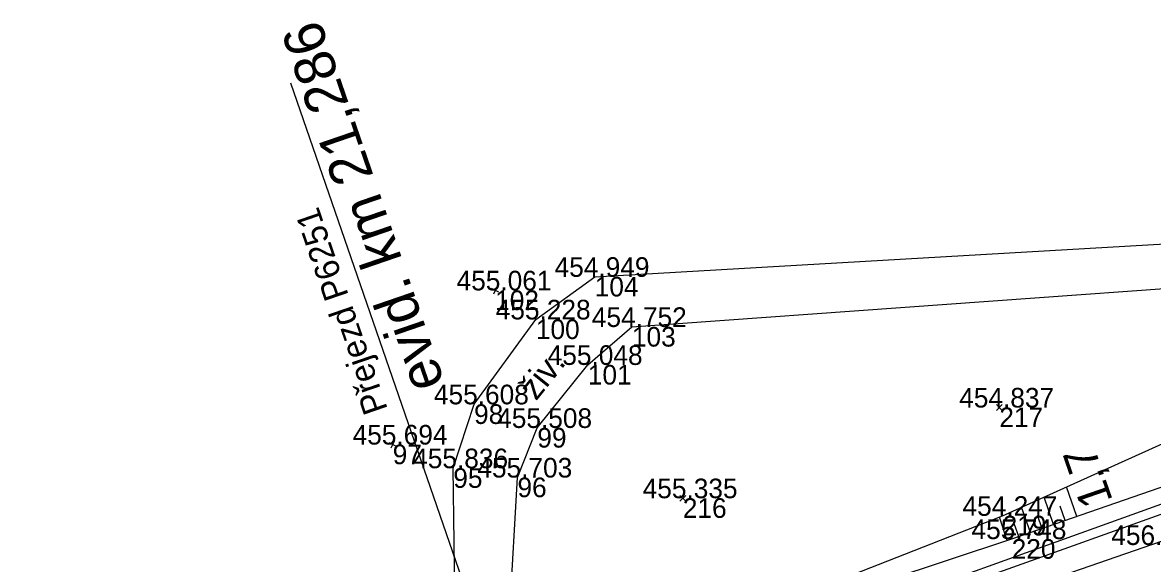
# Model space of a CAD drawing. Extents: x -751615 to -750797, y -1114905 to -1114561.
# Drawn here: x -750936.3 to -750867.3, y -1114593.7 to -1114560.6 of the extents above; entities that cross this region are included whole.
import ezdxf

# ---------------------------------------------------------------- set-up
doc = ezdxf.new("R2010")
doc.units = 0
for name, color, linetype in [('Vrstva 1', 7, 'Continuous'), ('Vrstva 4', 7, 'Continuous'), ('Vrstva 48', 7, 'Continuous'), ('Vrstva 49', 7, 'Continuous'), ('Vrstva 51', 7, 'Continuous'), ('Vrstva 60', 7, 'Continuous'), ('Vrstva 61', 7, 'Continuous')]:
    doc.layers.add(name, color=color, linetype=linetype)

msp = doc.modelspace()

# ---------------------------------------------------------------- linework, layer by layer
at = {"layer": 'Vrstva 1'}
msp.add_lwpolyline([(-750820.337, -1114576.326), (-750829.58, -1114579.518), (-750838.838, -1114582.712), (-750848.38, -1114586.005), (-750858.075, -1114589.346), (-750867.336, -1114592.541), (-750876.526, -1114595.715), (-750885.989, -1114598.98), (-750895.385, -1114602.229), (-750902.991, -1114604.843), (-750908.211, -1114606.647), (-750914.742, -1114608.898), (-750924.077, -1114612.114), (-750933.495, -1114615.368), (-750942.896, -1114618.61), (-750952.239, -1114621.829), (-750961.799, -1114625.127), (-750971.586, -1114628.505), (-750981.562, -1114631.945), (-750991.246, -1114635.286), (-751001.048, -1114638.665), (-751010.672, -1114641.989), (-751020.123, -1114645.246), (-751029.869, -1114648.612)], dxfattribs=at)
at = {"layer": 'Vrstva 4'}
msp.add_line((-750905.618, -1114605.751), (-750919.943, -1114564.3), dxfattribs=at)
for points in [[(-750824.673, -1114575.386), (-750842.852, -1114581.727), (-750861.561, -1114588.189), (-750880.945, -1114595.155), (-750899.361, -1114601.468), (-750902.908, -1114603.401)], [(-750824.563, -1114575.932), (-750842.715, -1114582.202), (-750861.411, -1114588.769), (-750880.904, -1114595.722), (-750899.175, -1114602.016), (-750902.908, -1114603.401)]]:
    msp.add_lwpolyline(points, dxfattribs=at)
at = {"layer": 'Vrstva 48'}
for p, q in [((-750871.896, -1114590.803), (-750872.523, -1114588.994)), ((-750873.313, -1114591.294), (-750873.896, -1114589.614)), ((-750874.731, -1114591.785), (-750875.268, -1114590.234)), ((-750872.605, -1114591.048), (-750872.907, -1114590.176)), ((-750876.149, -1114592.272), (-750876.626, -1114590.835)), ((-750874.022, -1114591.539), (-750874.302, -1114590.731)), ((-750875.439, -1114592.03), (-750875.697, -1114591.287))]:
    msp.add_line(p, q, dxfattribs=at)
at = {"layer": 'Vrstva 49'}
for p, q in [((-750907.222, -1114577.084), (-750907.672, -1114576.864)), ((-750907.337, -1114576.749), (-750907.557, -1114577.199)), ((-750876.809, -1114584.313), (-750876.455, -1114583.959)), ((-750876.455, -1114584.313), (-750876.809, -1114583.959)), ((-750913.482, -1114586.51), (-750913.932, -1114586.292)), ((-750913.598, -1114586.176), (-750913.816, -1114586.626)), ((-750896.151, -1114589.86), (-750895.797, -1114589.506)), ((-750895.797, -1114589.86), (-750896.151, -1114589.506))]:
    msp.add_line(p, q, dxfattribs=at)
for points in [[(-750902.869, -1114601.131), (-750876.43, -1114590.758), (-750847.082, -1114577.508), (-750846.11, -1114576.392), (-750828.341, -1114569.281)], [(-750829.333, -1114576.055), (-750875.877, -1114592.182), (-750902.869, -1114601.131)]]:
    msp.add_lwpolyline(points, dxfattribs=at)
at = {"layer": 'Vrstva 51'}
for points in [[(-750907.847, -1114605.676), (-750909.898, -1114596.967), (-750910.005, -1114587.848), (-750908.734, -1114583.94), (-750904.958, -1114578.749), (-750901.36, -1114576.145), (-750861.222, -1114573.82)], [(-750907.847, -1114605.676), (-750904.542, -1114604.506), (-750906.55, -1114596.602), (-750906.082, -1114588.417), (-750904.868, -1114585.385), (-750901.781, -1114581.531), (-750899.088, -1114579.21), (-750860.591, -1114576.435)]]:
    msp.add_lwpolyline(points, dxfattribs=at)
at = {"layer": 'Vrstva 60'}
for p, q in [((-750901.36, -1114576.145), (-750901.36, -1114576.145)), ((-750907.447, -1114576.974), (-750907.447, -1114576.974)), ((-750904.958, -1114578.749), (-750904.958, -1114578.749)), ((-750899.088, -1114579.21), (-750899.088, -1114579.21)), ((-750901.781, -1114581.531), (-750901.781, -1114581.531)), ((-750908.734, -1114583.94), (-750908.734, -1114583.94)), ((-750876.632, -1114584.136), (-750876.632, -1114584.136)), ((-750904.868, -1114585.385), (-750904.868, -1114585.385)), ((-750913.707, -1114586.401), (-750913.707, -1114586.401)), ((-750910.005, -1114587.848), (-750910.005, -1114587.848)), ((-750906.082, -1114588.417), (-750906.082, -1114588.417)), ((-750895.974, -1114589.683), (-750895.974, -1114589.683)), ((-750876.43, -1114590.758), (-750876.43, -1114590.758)), ((-750875.877, -1114592.182), (-750875.877, -1114592.182)), ((-750867.336, -1114592.541), (-750867.336, -1114592.541))]:
    msp.add_line(p, q, dxfattribs=at)

# ---------------------------------------------------------------- texts
at = {"layer": 'Vrstva 4'}
for s, height, rotation, p in [('evid. km 21,286', 2.5, 108.96662, (-750910.511, -1114582.641)), ('Přejezd P6251', 1.5, 108.94576, (-750913.997, -1114584.24))]:
    msp.add_text(s, height=height, rotation=rotation, dxfattribs=at).set_placement(p)
at = {"layer": 'Vrstva 48'}
msp.add_text('1,7', height=2, rotation=109.11066, dxfattribs=at).set_placement((-750869.679, -1114589.826))
at = {"layer": 'Vrstva 51'}
msp.add_text('živ.', height=1.5, rotation=51.30576, dxfattribs=at).set_placement((-750904.946, -1114583.768))
at = {"layer": 'Vrstva 60'}
for s, p in [('104', (-750901.36, -1114577.345)), ('102', (-750907.447, -1114578.174)), ('100', (-750904.958, -1114579.949)), ('103', (-750899.088, -1114580.41)), ('101', (-750901.781, -1114582.731)), ('98', (-750908.734, -1114585.14)), ('217', (-750876.632, -1114585.336)), ('99', (-750904.868, -1114586.585)), ('97', (-750913.707, -1114587.601)), ('95', (-750910.005, -1114589.048)), ('96', (-750906.082, -1114589.617)), ('216', (-750895.974, -1114590.883)), ('219', (-750876.43, -1114591.958)), ('220', (-750875.877, -1114593.382))]:
    msp.add_text(s, height=1.2, dxfattribs=at).set_placement(p)
at = {"layer": 'Vrstva 61'}
for s, p in [('454.949', (-750903.814, -1114576.145)), ('455.061', (-750909.804, -1114576.974)), ('455.228', (-750907.412, -1114578.749)), ('454.752', (-750901.536, -1114579.21)), ('455.048', (-750904.235, -1114581.531)), ('455.608', (-750911.188, -1114583.94)), ('454.837', (-750879.084, -1114584.136)), ('455.508', (-750907.322, -1114585.385)), ('455.694', (-750916.158, -1114586.401)), ('455.836', (-750912.457, -1114587.848)), ('455.703', (-750908.534, -1114588.417)), ('455.335', (-750898.43, -1114589.683)), ('454.247', (-750878.882, -1114590.758)), ('455.748', (-750878.331, -1114592.182)), ('456.656', (-750869.788, -1114592.541))]:
    msp.add_text(s, height=1.2, dxfattribs=at).set_placement(p)

doc.saveas('drawing.dxf')
